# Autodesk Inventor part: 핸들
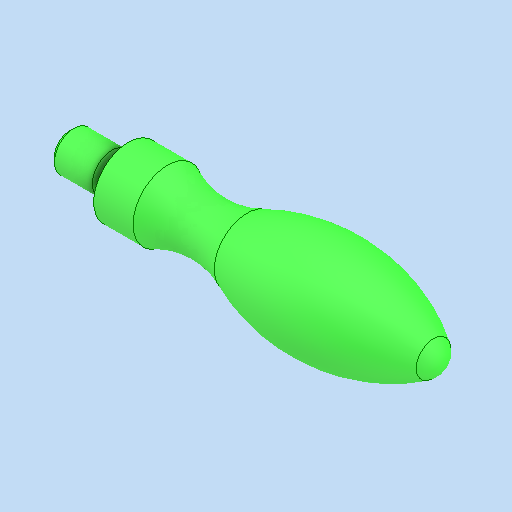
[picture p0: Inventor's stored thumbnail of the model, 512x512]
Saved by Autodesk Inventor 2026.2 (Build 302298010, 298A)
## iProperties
Created: 2026-08
Part Number: 핸들
Material: 스테인리스강
Document SubType Name: Modeling
Designer: PC-2-06
Density: 8.08 g/cm^3
Appearance: 기본값
Author: jhkim
Sending System: Autodesk Inventor 2027
Preprocessor: ST-DEVELOPER v20.1
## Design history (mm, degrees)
feature "솔리드1"
node "솔리드2"
